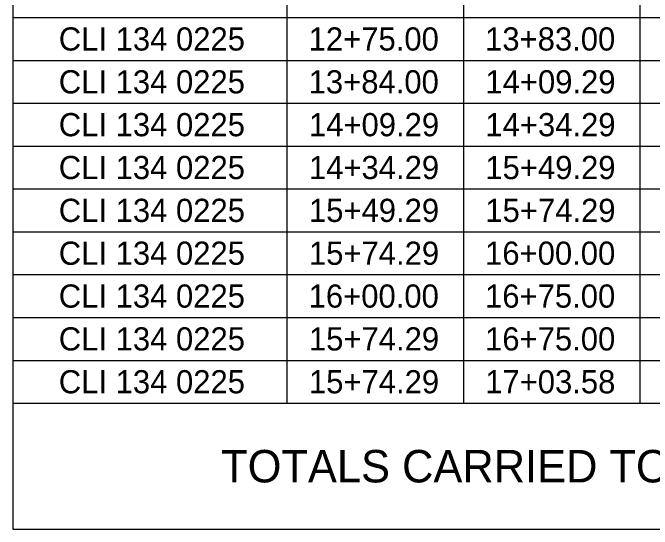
# Model space of a CAD drawing. Extents: x -27.3 to 69.3, y 0 to 30.
# Drawn here: x 42.08 to 45.939, y 15.036 to 18.153 of the extents above; entities that cross this region are included whole.
import ezdxf

# ---------------------------------------------------------------- set-up
doc = ezdxf.new("R2010")
doc.units = 0
doc.layers.add('Default', color=7, linetype='Continuous')

msp = doc.modelspace()

# ---------------------------------------------------------------- linework, layer by layer
at = {"layer": 'Default'}
for p, q in [((42.0798, 21.2276), (42.0798, 15.0364)), ((43.7344, 20.9689), (43.7344, 15.7969)), ((45.8641, 20.9689), (45.8641, 15.7969)), ((44.7992, 19.6759), (44.7992, 15.7969)), ((42.0798, 18.1243), (63.7531, 18.1243)), ((42.0798, 17.8657), (69.2574, 17.8657)), ((42.0798, 17.6071), (69.2574, 17.6071)), ((42.0798, 17.3485), (69.2574, 17.3485)), ((42.0798, 17.0899), (69.2574, 17.0899)), ((42.0798, 16.8313), (69.2574, 16.8313)), ((42.0798, 16.5727), (69.2574, 16.5727)), ((42.0798, 16.3141), (66.0793, 16.3141)), ((42.0798, 16.0555), (66.0793, 16.0555)), ((42.0798, 15.7969), (66.0793, 15.7969)), ((42.0798, 15.0364), (69.2574, 15.0364))]:
    msp.add_line(p, q, dxfattribs=at)

# ---------------------------------------------------------------- texts
for s, height, p in [('CLI 134 0225', 0.139948, (42.3574, 17.9251)), ('12+75.00', 0.13995, (43.8655, 17.9251)), ('13+83.00', 0.13995, (44.9303, 17.9251)), ('CLI 134 0225', 0.139948, (42.3574, 17.6665)), ('13+84.00', 0.13995, (43.8655, 17.6665)), ('14+09.29', 0.13995, (44.932, 17.6665)), ('CLI 134 0225', 0.139948, (42.3574, 17.4079)), ('14+09.29', 0.13995, (43.8672, 17.4079)), ('14+34.29', 0.13995, (44.932, 17.4079)), ('CLI 134 0225', 0.139948, (42.3574, 17.1493)), ('14+34.29', 0.13995, (43.8672, 17.1493)), ('15+49.29', 0.13995, (44.932, 17.1493)), ('CLI 134 0225', 0.139948, (42.3574, 16.8907)), ('15+49.29', 0.13995, (43.8672, 16.8907)), ('15+74.29', 0.13995, (44.932, 16.8907)), ('CLI 134 0225', 0.139948, (42.3574, 16.6321)), ('15+74.29', 0.13995, (43.8672, 16.6321)), ('16+00.00', 0.13995, (44.9303, 16.6321)), ('CLI 134 0225', 0.139948, (42.3574, 16.3735)), ('16+00.00', 0.13995, (43.8655, 16.3735)), ('16+75.00', 0.13995, (44.9303, 16.3735)), ('CLI 134 0225', 0.139948, (42.3574, 16.1149)), ('15+74.29', 0.13995, (43.8672, 16.1149)), ('16+75.00', 0.13995, (44.9303, 16.1149)), ('CLI 134 0225', 0.139948, (42.3574, 15.8563)), ('15+74.29', 0.13995, (43.8672, 15.8563)), ('17+03.58', 0.13995, (44.931, 15.8563)), ('TOTALS CARRIED TO GENERAL SUMMARY', 0.195928, (43.3375, 15.3187))]:
    msp.add_text(s, height=height, dxfattribs=at).set_placement(p)

doc.saveas('drawing.dxf')
